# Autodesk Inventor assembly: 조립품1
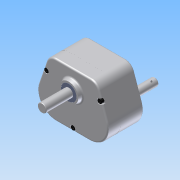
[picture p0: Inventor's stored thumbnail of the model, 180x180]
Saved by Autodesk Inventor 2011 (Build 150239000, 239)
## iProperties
Created: 2014-12
Part Number: 조립품1
Document SubType Name: Assembly
Designer: SDA24
Author: SDA24
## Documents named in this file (14)
- C:\441208V1038\조립품1.iam
- C:\441208V1038\M 5 x 35.ipt
- C:\441208V1038\멈춤링.ipt
- C:\441208V1038\메인기어.ipt
- C:\441208V1038\메인축.ipt
- C:\441208V1038\베어링- 6202.ipt
- C:\441208V1038\베어링- 6203.ipt
- C:\441208V1038\서브기어.ipt
- C:\441208V1038\서브축.ipt
- C:\441208V1038\오일시일-D-15.ipt
- C:\441208V1038\오일시일-D-17.ipt
- C:\441208V1038\커버.ipt
- C:\441208V1038\키5x5.ipt
- C:\441208V1038\부품1.ipt
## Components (15 placed, 6 different names)
1. KS B 1003 - 미터 M 5 x 35:1
2. KS B 1336 17 x 1:1 — 각도:5
3. KS B 2023 6202 - 15 x 35 x 11:1
4. KS B 2023 6203 - 17 x 40 x 12:1
5. KS B 2804 D D - 15 30 7:1
6. KS B 2804 D D - 17 30 8:1
7. KS B 2023 6203 - 17 x 40 x 12:2
8. KS B 2023 6202 - 15 x 35 x 11:2
9. KS B 2023 6203 - 17 x 40 x 12:3
10. KS B 2023 6203 - 17 x 40 x 12:4
11. KS B 1336 17 x 1:2 — 각도:4
12. KS B 1336 17 x 1:3
13. KS B 2804 D D - 15 30 7:2
14. KS B 1003 - 미터 M 5 x 35:2
15. KS B 1003 - 미터 M 5 x 35:3
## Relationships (2: Angle 2)
- 각도:4 [Angle]: KS B 1336 17 x 1:2
- 각도:5 [Angle]: KS B 1336 17 x 1:1
